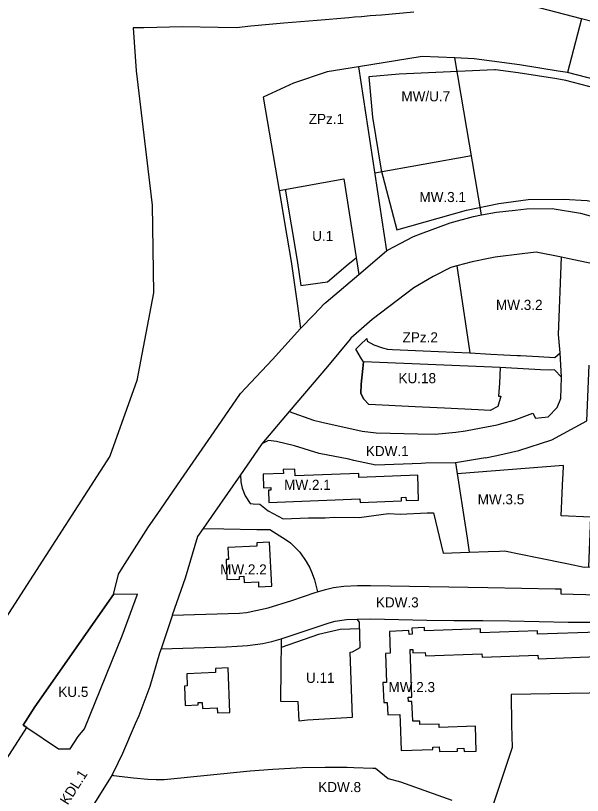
# Model space of a CAD drawing. Extents: x 7428239 to 7429836, y 5549133 to 5550853.
# Drawn here: x 7428481 to 7428761.2, y 5550266.4 to 5550651.7 of the extents above; entities that cross this region are included whole.
import ezdxf

# ---------------------------------------------------------------- set-up
doc = ezdxf.new("R2010")
doc.units = 0
for name, color, linetype in [('LIN_linie rozgraniczające', 7, 'Continuous'), ('LIN_nieprzekraczalna linia zabudowy', 7, 'Continuous'), ('LIN_obowiązująca linia zabudowy', 7, 'Continuous'), ('TXT_Oznaczenia Przeznaczenia', 7, 'Continuous')]:
    doc.layers.add(name, color=color, linetype=linetype)

msp = doc.modelspace()

# ---------------------------------------------------------------- linework, layer by layer
at = {"layer": 'LIN_linie rozgraniczające'}
for p, q in [((7428711.35, 5550553.22), (7428698.23, 5550630.85)), ((7428706.41, 5550582.46), (7428658.56, 5550573.87)), ((7428728.03, 5550555.59), (7428733.61, 5550556.2)), ((7428733.61, 5550556.2), (7428746.2, 5550556.39)), ((7428746.2, 5550556.39), (7428760.3, 5550554.13)), ((7428711.35, 5550553.22), (7428718.79, 5550554.57)), ((7428718.79, 5550554.57), (7428728.03, 5550555.59)), ((7428760.3, 5550554.13), (7428783.21, 5550547.57)), ((7428650.67, 5550523.77), (7428664.46, 5550535.43)), ((7428767.16, 5550528.95), (7428753.91, 5550531.68)), ((7428699.07, 5550528.05), (7428705.54, 5550485.05)), ((7428636.66, 5550511.9), (7428650.67, 5550523.77)), ((7428687.51, 5550522.89), (7428684.63, 5550521.22)), ((7428684.63, 5550521.22), (7428677.84, 5550517.27)), ((7428549.17, 5550514.78), (7428540.94, 5550471.5)), ((7428677.84, 5550517.27), (7428657.25, 5550501.54)), ((7428633.79, 5550509.47), (7428634.58, 5550510.14)), ((7428634.58, 5550510.14), (7428636.66, 5550511.9)), ((7428628.4, 5550503.89), (7428633.79, 5550509.47)), ((7428621.86, 5550497.12), (7428628.4, 5550503.89)), ((7428657.25, 5550501.54), (7428646.73, 5550492.29)), ((7428608.01, 5550481.84), (7428621.86, 5550497.12)), ((7428646.34, 5550491.82), (7428635.21, 5550478.43)), ((7428646.73, 5550492.29), (7428646.34, 5550491.82)), ((7428597.38, 5550470.5), (7428608.01, 5550481.84)), ((7428635.21, 5550478.43), (7428616.34, 5550456.12)), ((7428592.18, 5550464.95), (7428597.38, 5550470.5)), ((7428579.16, 5550446.03), (7428592.18, 5550464.95)), ((7428616.34, 5550456.12), (7428602.8, 5550440.12)), ((7428562.87, 5550422.49), (7428579.16, 5550446.03)), ((7428602.8, 5550440.12), (7428598.85, 5550434.44)), ((7428598.85, 5550434.44), (7428592.21, 5550424.89)), ((7428551.01, 5550405.23), (7428562.87, 5550422.49)), ((7428592.21, 5550424.89), (7428579.35, 5550406.38)), ((7428579.35, 5550406.38), (7428573.75, 5550398.33)), ((7428546.8, 5550399.1), (7428551.01, 5550405.23)), ((7428534.11, 5550379.24), (7428546.8, 5550399.1)), ((7428573.75, 5550398.33), (7428570.97, 5550394.33)), ((7428583.91, 5550398.18), (7428600.33, 5550397.8)), ((7428570.97, 5550394.33), (7428564.82, 5550373.79)), ((7428531.87, 5550375.79), (7428534.11, 5550379.24)), ((7428529.46, 5550365.72), (7428531.87, 5550375.79)), ((7428564.82, 5550373.79), (7428558.51, 5550355.46)), ((7428490.55, 5550310.24), (7428529.46, 5550365.72)), ((7428558.42, 5550355.22), (7428552.95, 5550338.92)), ((7428558.51, 5550355.46), (7428558.42, 5550355.22)), ((7428552.21, 5550336.74), (7428547.39, 5550320.17)), ((7428552.95, 5550338.92), (7428552.21, 5550336.74)), ((7428547.39, 5550320.17), (7428541.96, 5550305.79)), ((7428484.7, 5550301.17), (7428490.55, 5550310.24)), ((7428541.96, 5550305.79), (7428540.08, 5550301.81)), ((7428464.78, 5550266.18), (7428486.59, 5550299.96)), ((7428486.59, 5550299.96), (7428484.7, 5550301.17)), ((7428540.08, 5550301.81), (7428533.82, 5550287.07)), ((7428648.31, 5550280.23), (7428657.57, 5550279.84)), ((7428659.02, 5550279.84), (7428665.17, 5550274.78)), ((7428528.83, 5550276.64), (7428508.09, 5550243.65))]:
    msp.add_line(p, q, dxfattribs=at)
for points in [[(7428821.48, 5550628.82), (7428770.94, 5550647.44), (7428760.76, 5550650.1), (7428735.98, 5550656.57), (7428719.28, 5550662.75)], [(7428677.89, 5550653.4), (7428661.96, 5550652.04), (7428656.23, 5550651.55), (7428651.96, 5550651.19), (7428648.6, 5550650.9), (7428645.72, 5550650.66), (7428630.1, 5550649.33), (7428613.66, 5550647.93)], [(7428760.76, 5550650.1), (7428753.85, 5550623.63)], [(7428581.2, 5550645.84), (7428563.53, 5550646.16), (7428544.35, 5550645.66), (7428539.18, 5550645.62)], [(7428539.18, 5550645.62), (7428540.64, 5550624.51), (7428548.56, 5550558.06), (7428549.17, 5550514.78)], [(7428613.66, 5550647.93), (7428597.38, 5550646.55), (7428590.27, 5550645.74), (7428581.2, 5550645.84)], [(7428753.85, 5550623.63), (7428749.2, 5550624.37), (7428730.1, 5550627.38), (7428716.5, 5550629.23), (7428707.74, 5550630.42), (7428698.23, 5550630.85), (7428681.99, 5550631.58), (7428650.5, 5550626.41)], [(7428650.5, 5550626.41), (7428635.13, 5550623.89), (7428618.4, 5550618.43), (7428603.37, 5550611.46)], [(7428650.5, 5550626.41), (7428664.46, 5550535.43)], [(7428831.34, 5550598.74), (7428822.59, 5550602.83), (7428816.6, 5550604.92), (7428806.98, 5550608.3), (7428797.5, 5550611.31), (7428787, 5550614.62), (7428779.77, 5550616.92), (7428773.03, 5550618.67), (7428753.85, 5550623.63)], [(7428603.37, 5550611.46), (7428611.28, 5550565.37), (7428643.32, 5550571.13), (7428650.67, 5550523.77)], [(7428611.28, 5550565.37), (7428615.15, 5550542.81), (7428617.31, 5550530.22), (7428620.31, 5550508.37), (7428621.86, 5550497.12)], [(7428664.46, 5550535.43), (7428664.87, 5550535.78), (7428677.74, 5550542.66), (7428681.16, 5550543.91), (7428695.88, 5550549.29), (7428707.32, 5550552.49), (7428711.35, 5550553.22)], [(7428753.91, 5550531.68), (7428750.88, 5550532.3), (7428738.36, 5550534.87), (7428731.46, 5550534.01), (7428718.15, 5550532.41), (7428714.76, 5550531.73), (7428706.68, 5550530.12), (7428699.07, 5550528.05), (7428696.23, 5550527.29), (7428687.51, 5550522.89)], [(7428616.34, 5550456.12), (7428628.27, 5550451.88), (7428632.38, 5550450.82), (7428652.35, 5550446.43), (7428659.35, 5550445.6), (7428679.88, 5550445.01), (7428688.36, 5550444.97), (7428698.65, 5550445.86), (7428703.36, 5550446.57), (7428711.11, 5550448.01), (7428719.06, 5550449.58), (7428721.36, 5550450.19), (7428727.46, 5550451.91), (7428736.65, 5550455.37), (7428737.96, 5550452.82), (7428744.29, 5550453.49), (7428748.75, 5550458.12), (7428750.55, 5550462.5), (7428750.87, 5550473.12), (7428750.21, 5550485.04), (7428749.43, 5550494.21), (7428750.88, 5550532.3)], [(7428750.87, 5550473.12), (7428747.5, 5550476.63), (7428745.23, 5550476.51), (7428740.55, 5550476.75), (7428723.34, 5550477.65), (7428720.64, 5550477.79), (7428720.18, 5550470.16), (7428719.79, 5550463.64), (7428720.95, 5550463.65), (7428719.47, 5550458.58), (7428715.66, 5550456.6), (7428709.77, 5550456.88), (7428693.12, 5550457.69), (7428678.54, 5550458.38), (7428655.63, 5550459.57), (7428653.21, 5550462.2), (7428651.73, 5550464.97), (7428651.81, 5550469.55), (7428652.6, 5550477.43), (7428653.04, 5550480.6), (7428652.08, 5550482.22), (7428649.28, 5550486.9), (7428651.34, 5550488.99), (7428654.61, 5550492.15), (7428654.8, 5550490.86), (7428658.07, 5550489.13), (7428662.42, 5550487.51), (7428664.84, 5550487), (7428667.41, 5550486.82), (7428690.05, 5550485.84), (7428705.54, 5550485.05), (7428715.89, 5550484.5), (7428722.31, 5550484.16), (7428729.01, 5550483.81), (7428730.65, 5550483.72), (7428739.51, 5550483.26), (7428747.56, 5550482.86), (7428750.21, 5550485.04)], [(7428713.31, 5550433.25), (7428718.88, 5550434.46), (7428729.82, 5550436.8), (7428746.05, 5550442.15), (7428763.33, 5550451.58), (7428764.53, 5550479.02)], [(7428540.94, 5550471.5), (7428527.62, 5550433.97), (7428484.97, 5550367.83), (7428424.73, 5550274.49), (7428379.41, 5550200.89), (7428351.69, 5550140.08), (7428336.04, 5550081.17)], [(7428713.31, 5550433.25), (7428698.48, 5550430.82), (7428683.66, 5550430.53), (7428681.57, 5550430.45), (7428659.09, 5550429.59), (7428648.27, 5550431.9), (7428645.79, 5550432.53), (7428631.06, 5550435.37), (7428618.98, 5550439.15), (7428610.08, 5550441.33), (7428606.08, 5550441.71), (7428602.8, 5550440.12)], [(7428698.48, 5550430.82), (7428704.2, 5550393.46), (7428705.26, 5550386.53)], [(7428592.21, 5550424.89), (7428592.34, 5550421.43), (7428593, 5550418.24), (7428594.49, 5550414.49), (7428596.93, 5550410.65), (7428598.41, 5550410.48), (7428601.83, 5550410.37), (7428605.88, 5550407.08), (7428613.32, 5550403.11)], [(7428613.32, 5550403.11), (7428625.75, 5550403.58), (7428634.13, 5550403.5), (7428638.48, 5550403.88), (7428650.8, 5550403.72), (7428665.4, 5550405.77), (7428671.06, 5550405.31), (7428684.46, 5550405.98), (7428687.55, 5550406.08), (7428692.47, 5550386.04), (7428705.26, 5550386.53), (7428714.6, 5550386.89), (7428720.24, 5550387.11), (7428722.64, 5550387.21), (7428738.83, 5550383.93), (7428754.33, 5550380.81), (7428762.17, 5550379.23), (7428788.4, 5550380.41), (7428797.19, 5550380.81)], [(7428573.75, 5550398.33), (7428583.91, 5550398.18)], [(7428600.33, 5550397.8), (7428602.52, 5550397.82), (7428604.11, 5550397.81), (7428606.76, 5550397.74)], [(7428606.76, 5550397.74), (7428614.84, 5550392.72), (7428616.87, 5550391.18), (7428618.77, 5550389.48), (7428621.48, 5550386.54), (7428624.75, 5550382.04), (7428626.51, 5550378.91), (7428627.7, 5550376.14), (7428628.72, 5550373), (7428630.35, 5550367.04)], [(7428558.51, 5550355.46), (7428591.65, 5550356.41), (7428595.19, 5550356.8), (7428595.95, 5550356.93), (7428605.9, 5550359.04), (7428617.58, 5550362.81), (7428629.09, 5550366.62), (7428630.35, 5550367.04), (7428634.2, 5550368.21), (7428638.26, 5550369.12), (7428643.23, 5550369.79), (7428649.99, 5550370.19), (7428656.5, 5550370.18), (7428714.45, 5550369.11), (7428747.81, 5550368.53), (7428750.61, 5550368.5), (7428750.63, 5550365.96), (7428768.98, 5550365.54)], [(7428486.59, 5550299.96), (7428502.28, 5550289.37), (7428506.45, 5550289.51), (7428507.96, 5550289.35), (7428512, 5550295.45), (7428515.16, 5550299.24), (7428533.64, 5550345.25), (7428541.36, 5550365.79), (7428529.46, 5550365.72)], [(7428612.31, 5550343.84), (7428626.17, 5550348.36), (7428629.08, 5550349.34), (7428636.05, 5550351.67), (7428639.05, 5550352.55), (7428644.62, 5550353.35), (7428649.94, 5550353.45)], [(7428649.94, 5550353.45), (7428656.43, 5550353.73), (7428684.28, 5550352.94), (7428697.62, 5550352.87), (7428711.92, 5550352.78), (7428725.12, 5550352.65), (7428739.82, 5550352.33), (7428754.12, 5550352.06), (7428768.05, 5550352.1), (7428769.51, 5550347.13), (7428769.78, 5550341.08), (7428774.92, 5550341.24), (7428782.83, 5550341.17)], [(7428651.39, 5550339.55), (7428651.02, 5550351.94), (7428649.94, 5550353.45)], [(7428552.95, 5550338.92), (7428579.84, 5550339.69), (7428585.18, 5550339.89), (7428590.52, 5550340.09), (7428593.13, 5550340.25), (7428595.74, 5550340.42), (7428603.26, 5550341.5), (7428607.76, 5550342.44), (7428612.31, 5550343.84)], [(7428612.31, 5550343.84), (7428612.3, 5550341.79), (7428612.14, 5550329.33), (7428611.92, 5550312.99)], [(7428647.5, 5550305.04), (7428646.5, 5550337.28), (7428647.49, 5550337.33), (7428651.39, 5550339.55)], [(7428774.34, 5550317.09), (7428726, 5550316.32), (7428726.24, 5550301.32), (7428726.42, 5550290.09), (7428716.31, 5550259.45)], [(7428611.92, 5550312.99), (7428620.61, 5550312.86), (7428620.99, 5550303.34), (7428625.31, 5550303.84), (7428647.5, 5550305.04)], [(7428533.82, 5550287.07), (7428531.64, 5550282.36), (7428528.83, 5550276.64)], [(7428528.83, 5550276.64), (7428529.49, 5550276.25), (7428539.25, 5550275.02), (7428546.46, 5550274.43), (7428550.6, 5550274.26), (7428554.41, 5550274.35), (7428596.93, 5550278.5), (7428608.25, 5550279.46), (7428622.61, 5550280.2), (7428633.99, 5550280.44), (7428644.92, 5550280.36), (7428648.31, 5550280.23)], [(7428657.57, 5550279.84), (7428659.02, 5550279.84)], [(7428665.17, 5550274.78), (7428671.25, 5550273.2), (7428696.63, 5550264.05)]]:
    msp.add_lwpolyline(points, dxfattribs=at)
at = {"layer": 'LIN_nieprzekraczalna linia zabudowy'}
for p, q in [((7428653.04, 5550480.6), (7428652.6, 5550477.43)), ((7428720.64, 5550477.79), (7428653.04, 5550480.6)), ((7428652.6, 5550477.43), (7428651.81, 5550469.55))]:
    msp.add_line(p, q, dxfattribs=at)
for points in [[(7428717.84, 5550624.92), (7428670.71, 5550622.85), (7428655.67, 5550621.45), (7428657.52, 5550601.6), (7428661.69, 5550575.4), (7428669.52, 5550545.96)], [(7428820.96, 5550599.16), (7428815.28, 5550601.14), (7428805.71, 5550604.51), (7428796.29, 5550607.5), (7428785.79, 5550610.81), (7428778.66, 5550613.08), (7428772.03, 5550614.8), (7428753.03, 5550619.71), (7428748.57, 5550620.42), (7428729.52, 5550623.42), (7428718.27, 5550624.95), (7428717.84, 5550624.92)], [(7428614.23, 5550565.9), (7428620.28, 5550530.68), (7428621.97, 5550518.36), (7428635.24, 5550520.19), (7428645.49, 5550529), (7428649.38, 5550532.05), (7428649.38, 5550532.05)], [(7428669.52, 5550545.96), (7428703.88, 5550555.62), (7428719.96, 5550558.83), (7428734.33, 5550560.82), (7428751.87, 5550560.96), (7428763.53, 5550560.38), (7428788.54, 5550554.92), (7428894.78, 5550521.44)], [(7428753.91, 5550531.68), (7428750.88, 5550532.3), (7428738.36, 5550534.87), (7428731.46, 5550534.01), (7428718.15, 5550532.41), (7428714.76, 5550531.73), (7428706.68, 5550530.12), (7428699.07, 5550528.05)], [(7428651.81, 5550469.55), (7428651.73, 5550464.97), (7428653.21, 5550462.2), (7428655.63, 5550459.57)], [(7428764.39, 5550379.33), (7428765.46, 5550403.92), (7428750.66, 5550404.56), (7428751.5, 5550423.17), (7428751.65, 5550425), (7428751.88, 5550429.36), (7428699.31, 5550425.39)], [(7428529.46, 5550365.72), (7428490.55, 5550310.24), (7428484.7, 5550301.17), (7428486.59, 5550299.96), (7428502.28, 5550289.37), (7428506.45, 5550289.51), (7428507.96, 5550289.35), (7428512, 5550295.45), (7428515.16, 5550299.24), (7428533.64, 5550345.25), (7428541.36, 5550365.79), (7428529.46, 5550365.72)], [(7428651.03, 5550348.78), (7428641.5, 5550348.39), (7428630.81, 5550345.94), (7428612.27, 5550339.49)]]:
    msp.add_lwpolyline(points, dxfattribs=at)
at = {"layer": 'LIN_obowiązująca linia zabudowy'}
for points in [[(7428603.6, 5550418.38), (7428607.2, 5550418.52), (7428607.24, 5550417.32), (7428606.04, 5550417.27), (7428606.26, 5550411.21), (7428651.22, 5550412.91), (7428651.28, 5550411.16), (7428671.82, 5550411.93), (7428671.76, 5550413.66), (7428674, 5550413.75), (7428674.07, 5550412.12), (7428680.26, 5550412.36), (7428679.8, 5550424.65), (7428650.76, 5550423.55), (7428650.69, 5550425.47), (7428619.2, 5550424.28), (7428619.07, 5550427.69), (7428613.34, 5550427.47), (7428613.42, 5550425.46), (7428603.35, 5550425.08)], [(7428585.99, 5550388.93), (7428586.22, 5550382.97), (7428585.08, 5550382.93), (7428585.47, 5550373.08), (7428591.79, 5550373.33), (7428591.74, 5550374.63), (7428593.91, 5550374.71), (7428594.03, 5550371.63), (7428601.11, 5550371.91), (7428601.18, 5550369.51), (7428607.62, 5550369.74), (7428606.5, 5550391.54), (7428600.21, 5550391.2), (7428600.27, 5550389.5)], [(7428565.61, 5550326.52), (7428565.84, 5550320.52), (7428564.53, 5550320.47), (7428564.91, 5550310.84), (7428571.29, 5550311.1), (7428571.24, 5550312.32), (7428573.28, 5550312.4), (7428573.39, 5550309.4), (7428580.67, 5550309.68), (7428580.77, 5550307.18), (7428586.93, 5550307.42), (7428586.06, 5550329.39), (7428579.81, 5550329.14), (7428579.89, 5550327.09)]]:
    msp.add_lwpolyline(points, close=True, dxfattribs=at)
msp.add_lwpolyline([(7428768.9, 5550347.15), (7428739.03, 5550346.04), (7428738.97, 5550347.78), (7428710.91, 5550346.78), (7428710.84, 5550348.66), (7428683.2, 5550347.68), (7428683.12, 5550349.39), (7428676.94, 5550349.11), (7428677.07, 5550346.05), (7428675.57, 5550345.98), (7428675.49, 5550347.87), (7428665.86, 5550347.44), (7428666.18, 5550336.67), (7428663.87, 5550336.61), (7428664.42, 5550322.19), (7428662.62, 5550322.13), (7428662.99, 5550312.28), (7428664.78, 5550312.35), (7428665.01, 5550306.22), (7428671.01, 5550306.4), (7428671.14, 5550302.85), (7428671.58, 5550288.63), (7428687.33, 5550289.12), (7428687.29, 5550290.3), (7428690.48, 5550290.4), (7428690.55, 5550288.08), (7428699.48, 5550288.36), (7428699.44, 5550289.61), (7428702.68, 5550289.71), (7428702.73, 5550288.12), (7428708.75, 5550288.3), (7428708.37, 5550300.57), (7428690.47, 5550300.01), (7428690.42, 5550301.67), (7428680.92, 5550301.38), (7428680.86, 5550303.15), (7428677.32, 5550303.04), (7428677.18, 5550306.68), (7428676.95, 5550312.88), (7428675.21, 5550312.82), (7428675.13, 5550314.93), (7428676.93, 5550314.99), (7428676.06, 5550338.54), (7428677.38, 5550338.59), (7428677.44, 5550336.84), (7428683.55, 5550337.07), (7428683.61, 5550335.4), (7428711.56, 5550336.44), (7428711.63, 5550334.67), (7428739.24, 5550335.69), (7428739.31, 5550333.91), (7428768.55, 5550335)], dxfattribs=at)

# ---------------------------------------------------------------- texts
at = {"layer": 'TXT_Oznaczenia Przeznaczenia'}
for s, p in [('MW/U.7', (7428671.73, 5550609.4)), ('ZPz.1', (7428625.95, 5550598.17)), ('MW.3.1', (7428680.64, 5550559.6)), ('U.1', (7428627.64, 5550540.36)), ('MW.3.2', (7428718.49, 5550506.3)), ('ZPz.2', (7428672.33, 5550490.27)), ('KU.18', (7428670.29, 5550470.11)), ('MW.2.1', (7428613.78, 5550417.37)), ('MW.3.5', (7428709.46, 5550410.23)), ('MW.2.2', (7428582.13, 5550375.59)), ('U.11', (7428624.6, 5550322.02)), ('MW.2.3', (7428665.35, 5550317.47)), ('KU.5', (7428502.15, 5550315.08))]:
    msp.add_text(s, height=5, dxfattribs=at).set_placement(p)
for s, rotation, p in [('KDW.1', 359.9903, (7428654.17, 5550434.07)), ('KDW.3', 359.9903, (7428659.12, 5550359.31)), ('KDL.1', 57.4454, (7428506.8, 5550261.35)), ('KDW.8', 359.9903, (7428630.63, 5550268.06))]:
    msp.add_text(s, height=5, rotation=rotation, dxfattribs=at).set_placement(p)

doc.saveas('drawing.dxf')
